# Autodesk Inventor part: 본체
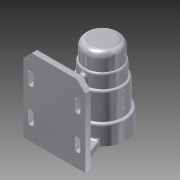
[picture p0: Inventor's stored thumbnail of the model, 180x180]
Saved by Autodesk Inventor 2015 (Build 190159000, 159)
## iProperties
Created: 2017-09
Part Number: 본체
Material: 알루미늄 6061
Document SubType Name: Modeling
Designer: Administrator
Density: 2.7 g/cm^3
Appearance: 알루미늄 - 평지
Mass: 695.321 g
Surface Area: 712.363 cm^2
Volume: 257.526 cm^3
Author: Administrator
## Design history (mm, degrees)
sketch "스케치1"
  geometry: L1 (-45, -56)-(45, -56); L2 (45, -56)-(45, 56); L3 (45, 56)-(-45, 56); L4 (-45, 56)-(-45, -56); L5 (-45, -56)-(45, 56); L6 (45, -56)-(-45, 56); 1 further point
  constraints: 12 end point, 2 midpoint, 2 parallel, 1 horizontal, 1 perpendicular
  dimensions: "d0" = 90 distance of L3.end L2.end; "d1" = 112 distance of L2.end L1.end
extrude "돌출1" new body sketch "스케치1" distance "d2" = 8; taper "d3" = 0 deg
sketch "스케치2"
  geometry: 1 further point
sketch "스케치3"
  geometry: L1 (0, -56)-(-8, -56) reference; L2 (-8, -56)-(-8, 56) reference; L3 (-8, 56)-(0, 56) reference; L4 (0, 56)-(0, -56) reference; L5 (62, -56)-(83, -56); L6 (83, -56)-(83, -41); L7 (83, -41)-(86, -41); L8 (86, -41)-(86, 13); L9 (86, 13)-(83, 13); L10 (83, 13)-(83, 25); L11 (83, 25)-(79.5, 25); L12 (79.5, 25)-(79.5, 43); L13 (79.5, 43)-(78, 43); L14 (78, 43)-(78, 47); L15 (78, 47)-(72.5, 47); L16 (72.5, 47)-(72.5, 50); L17 (72.5, 50)-(62, 50); L18 (83, -56)-(117.075, -56); L19 (62, 139.479)-(62, -56.834); L20 (62, 56)-(87, 56); L21 (87, 56)-(87, 31); L22 (87, 31)-(89, 31); L23 (89, 31)-(89, 11); L24 (89, 11)-(92, 11); L25 (92, 11)-(92, -28); L26 (92, -28)-(96, -28); L27 (83, -56)-(96, -56); L28 (96, -56)-(96, -28); 1 further point
  constraints: 48 end point, 18 perpendicular, 6 point on line, 2 horizontal, 2 vertical
  dimensions: "d4" = 70 distance from line of L2 L5.start; "d5" = 15 distance of L5.end L6.end; "d6" = 54 distance between parallel lines of L9 L7; "d7" = 12 distance between parallel lines of L11 L9; "d8" = 18 distance between parallel lines of L13 L11; "d9" = 4 distance of L13.end L14.end; "d10" = 3 distance of L15.end L16.end; "d11" = 42 diameter of L6 L19; "d12" = 21 diameter of L16 L19; "d13" = 32 diameter of L14 L19; "d14" = 35 diameter of L12 L19; "d15" = 42 diameter of L10 L19 (derived); "d16" = 48 diameter of L8 L19; "d17" = 112 distance between parallel lines of L20 L27; "d18" = 50 diameter of L21 L19; "d19" = 54 diameter of L23 L19; "d20" = 60 diameter of L25 L19; "d21" = 25 distance of L20.end L21.end; "d22" = 45 distance from line of L20 L24.end; "d23" = 84 distance between parallel lines of L26 L20; "d24" = 68 diameter of L28 L19
revolve "회전1" sketch "스케치3" stored, may be unused: angle "d25" = 90 deg
sketch "스케치4"
  geometry: L1 (0, -8)-(0, 0) reference; L2 (0, 0)-(90, 0) reference; L3 (90, 0)-(90, -8) reference; L4 (90, -8)-(0, -8) reference; L5 (90, 0)-(80, 0); L6 (0, 0)-(90, 0) reference; L7 (80, 0)-(66.9, 35.992); L8 (0, 0)-(10, 0); L9 (10, 0)-(23.1, 35.992); C1 r 21 at (45, 62) reference; A1 r 34 centre (45, 62) between (66.9, 35.992) and (23.1, 35.992) reference; 1 further point
  constraints: 8 end point, 2 point on circle, 2 point on line
  dimensions: "d26" = 10 distance of L2.end L5.end; "d27" = 110 deg angle of L5 L7; "d28" = 10 distance of L1.end L8.end
extrude "돌출2" join sketch "스케치4" distance "d30" = 8; taper "d31" = 0 deg
sketch "스케치5"
  geometry: L1 (-8, 56)-(0, 56) reference; L2 (0, 56)-(0, -48) reference; L3 (0, -48)-(28, -48) reference; L4 (28, -48)-(28, -28) reference; L5 (28, -28)-(32, -28) reference; L6 (32, -28)-(32, 11) reference; L7 (32, 11)-(35, 11) reference; L8 (35, 11)-(35, 31) reference; L9 (35, 31)-(37, 31) reference; L10 (37, 31)-(37, 56) reference; L11 (37, 56)-(87, 56) reference; L12 (87, 56)-(87, 31) reference; L13 (87, 31)-(89, 31) reference; L14 (89, 31)-(89, 11) reference; L15 (89, 11)-(92, 11) reference; L16 (92, 11)-(92, -28) reference; L17 (92, -28)-(96, -28) reference; L18 (96, -28)-(96, -56) reference; L19 (96, -56)-(83, -56) reference; L20 (83, -56)-(83, -41) reference; L21 (83, -41)-(86, -41) reference; L22 (86, -41)-(86, 13) reference; L23 (86, 13)-(83, 13) reference; L24 (83, 13)-(83, 25) reference; L25 (83, 25)-(79.5, 25) reference; L26 (79.5, 25)-(79.5, 43) reference; L27 (79.5, 43)-(78, 43) reference; L28 (78, 43)-(78, 47) reference; L29 (78, 47)-(72.5, 47) reference; L30 (72.5, 47)-(72.5, 50) reference; L31 (72.5, 50)-(51.5, 50) reference; L32 (51.5, 50)-(51.5, 47) reference; L33 (51.5, 47)-(46, 47) reference; L34 (46, 47)-(46, 43) reference; L35 (46, 43)-(44.5, 43) reference; L36 (44.5, 43)-(44.5, 25) reference; L37 (44.5, 25)-(41, 25) reference; L38 (41, 25)-(41, 13) reference; L39 (41, 13)-(38, 13) reference; L40 (38, 13)-(38, -41) reference; L41 (38, -41)-(41, -41) reference; L42 (41, -41)-(41, -56) reference; L43 (41, -56)-(-8, -56) reference; L44 (-8, -56)-(-8, 56) reference; L45 (0, 56)-(0, 34); L46 (0, -56)-(0, 56) reference; L47 (0, 34)-(38, 23.818); L48 (0, 34)-(39.34, 34); L49 (-8, 56)-(0, 56) reference; L50 (0, 56)-(0, -48) reference; L51 (0, -48)-(28, -48) reference; L52 (28, -48)-(28, -28) reference; L53 (28, -28)-(32, -28) reference; L54 (32, -28)-(32, 11) reference; L55 (32, 11)-(35, 11) reference; L56 (35, 11)-(35, 31) reference; L57 (35, 31)-(37, 31) reference; L58 (37, 31)-(37, 56) reference; L59 (37, 56)-(87, 56) reference; L60 (87, 56)-(87, 31) reference; L61 (87, 31)-(89, 31) reference; L62 (89, 31)-(89, 11) reference; L63 (89, 11)-(92, 11) reference; L64 (92, 11)-(92, -28) reference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; 1 further point
  constraints: 10 end point, 1 equal length, 1 horizontal, 1 midpoint, 1 point on line, 1 vertical
  dimensions: "d32" = 22 distance of L1.end L45.end; "d72" = 15 deg angle of L47 L48
  node "절단 모서리 투영3"
  node "절단 모서리 투영7"
  node "절단 모서리 투영8"
sketch "스케치6"
  geometry: L1 (-45, -56)-(-45, 56) reference; L2 (-45, 56)-(-35, 56) reference; L3 (-35, 48)-(-35, 56) reference; L4 (35, 48)-(-35, 48) reference; L5 (35, 56)-(35, 48) reference; L6 (35, 56)-(45, 56) reference; L7 (45, 56)-(45, -56) reference; L8 (45, -56)-(-45, -56) reference; L9 (-35, 56)-(35, 56) reference; L10 (-45, 56)-(-45, 34.95); L11 (-45, -56)-(-45, 56) reference; L12 (45, -56)-(-45, -56) reference; L13 (0, -56)-(-34, -56); L14 (-45, 22.956)-(-45, -17.044); L15 (-45, -17.044)-(-38, -17.044); L16 (-45, 56)-(-45, -56) reference; L17 (-34, 22.956)-(-34, -39.008); L18 (-30, -17.044)-(-30, -29.044); L19 (-38, -17.044)-(-38, -29.044); L20 (-30, -17.044)-(-30, -29.044); L21 (-38, -29.036)-(-37.974, -16.593); L22 (-45, 56)-(-45, 32); L23 (-45, 32)-(-34, 32); L24 (-34, 32)-(-34, 28.056); L25 (-34, 32)-(-34, 20); L26 (-30, 32)-(-30, 20); L27 (-38, 32)-(-38, 20); L28 (0, 28.056)-(-30, 28.056); L29 (-33.331, 28.056)-(-34, 28.056); C1 r 4 at (-34, -29.044); A1 r 4 centre (-34, -29.044) between (-38, -29.036) and (-30, -29.044); A2 r 4 centre (-34, -17.044) between (-30, -17.044) and (-38, -17.044); A3 r 4 centre (-34, 20) between (-38, 20) and (-30, 20); A4 r 4 centre (-34, 32) between (-34, 28) and (-33.331, 28.056); A5 r 4 centre (-34, 32) between (-30, 32) and (-38, 32); 2 further points
  constraints: 34 end point, 11 point on circle, 10 point on line, 6 centre point, 6 tangent, 4 coincident, 4 vertical, 3 horizontal, 2 perpendicular, 1 midpoint, 1 parallel, 3 other
  dimensions: "d36" = 34 distance of L13.start L13.end; "d44" = 40 distance of L14.start L14.end; "d49" = 12 distance of L18.start L18.end; "d50" = 12 distance of L15.end L19.end; "d87" = 24 distance of L1.end L22.end; "d88" = 34 distance of L28.start L24.end; "d90" = 12 distance of L25.start L25.end; "d91" = 8 diameter of A3
  node "절단 모서리 투영4"
chamfer "모따기1" distance "d53" = 12; stored, may be unused: second distance "d54" = 2, angle "d55" = 45 deg
sketch "스케치7" dims "d56" = 52
  geometry: L1 (0, 8)-(10, 8) reference; L2 (10, 8)-(23.1, 43.992) reference; L3 (66.9, 43.992)-(80, 8) reference; L4 (80, 8)-(90, 8) reference; L5 (90, 8)-(90, 0) reference; L6 (90, 0)-(0, 0) reference; L7 (0, 0)-(0, 8) reference; L8 (0, 8)-(10, 8) reference; L9 (10, 8)-(23.1, 43.992) reference; L10 (66.9, 43.992)-(80, 8) reference; L11 (80, 8)-(90, 8) reference; L12 (90, 8)-(90, 0) reference; L13 (90, 0)-(0, 0) reference; L14 (0, 0)-(0, 8) reference; C1 r 21 at (45, 70) reference; C2 r 21 at (45, 70) reference; A1 r 34 centre (45, 70) between (66.9, 43.992) and (23.1, 43.992) reference; A2 r 34 centre (45, 70) between (66.9, 43.992) and (23.1, 43.992) reference; 3 further points
  constraints: 1 coincident, 1 vertical alignment, 2 other
hole "구멍1" sketch "스케치7" at (45, 96) diameter "d57" = 3.242; stored, may be unused: countersink angle "d61" = 90 deg, drill point angle "d63" = 118 deg; dims "d58" = 8, "d59" = 4, "d60" = 2, "d62" = 11.8
fillet "모깎기3" dims "d69" = 3
fillet "모깎기4" dims "d70" = 0.3
extrude "돌출6" join sketch "스케치5" stored distance "d73" = 8; taper "d74" = 0 deg
fillet "모깎기5" dims "d75" = 3
fillet "모깎기6" dims "d76" = 3
fillet "모깎기7" dims "d77" = 9
fillet "모깎기8" dims "d78" = 3
node "작업 평면1"
node "작업 평면2"
sketch "스케치8"
  geometry: L1 (-70, -47.5)-(-70, 52.5) reference; L2 (-24.711, -47.5)-(34, -47.5) reference; 2 further points
  constraints: 1 other
  dimensions: "d80" = 70 distance from line of L1 point (0, 0.5); "d81" = 48 distance from line of L2 point (0, 0.5)
feature "엠보싱1" sketch "스케치8" dims "d0" = 90, "d1" = 112, "d4" = 70, "d5" = 15, "d6" = 54, "d7" = 12, "d8" = 18, "d9" = 4, "d10" = 3, "d11" = 42, "d12" = 21, "d13" = 32, "d14" = 35, "d15" = 42 (derived), "d16" = 48, "d17" = 112, "d18" = 50, "d19" = 54, "d20" = 60, "d21" = 25, "d22" = 45, "d23" = 84, "d24" = 68, "d82" = 0.5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
extrude "돌출7" cut sketch "스케치6" distance "d92" = 8; taper "d93" = 0 deg
node "솔리드1"
pattern_circular "원형 패턴1" dims angle "d65" = 360 deg
mirror "대칭2"
node "절단 모서리 투영1"
node "절단 모서리 투영2"
node "절단 모서리 투영5"
node "절단 모서리 투영6"
other parameters: "d29" = 110 deg, "d79" = 92.75, "d89" = 8
